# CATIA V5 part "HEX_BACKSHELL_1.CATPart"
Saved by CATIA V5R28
Part number: HEX_BACKSHELL_1
Revision: ---
Publications: "Logical Termination.1", "BaCP", "Face_generated(BaCP)", "Axis_generated(BaCP)", "Face_generated(BaCP).1", "BCP", "BCPRPoint_generated(BCP)", "BCPPlane_generated(BCP)", "SOCK", "SOCKRPoint_generated(SOCK)", "SOCKRLine_generated(SOCK)"
Bounding box of the stored display mesh (mm): x 0 to 28.448, y -13.335 to 13.335, z -24.638 to 12.832
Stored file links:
  C:\Users\ajc8720\Documents\BOEING_WORK\0001-2CES\004-AP242\Boeing-Generic_Harness_R3\HEX_BACKSHELL_1.CATPart
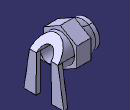
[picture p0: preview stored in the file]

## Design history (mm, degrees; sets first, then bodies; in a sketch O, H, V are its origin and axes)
Parameters
  PartNumber = "HEX_BACKSHELL_1"
Set1 "EGF"
  Set2 "BaCP"
    Point1 "BaCPRPoint": (6.604, 0, 0)
    Plane1 "BaCPCPlane": type OffsetPt, RefPlane yz-plane, RefPoint Point1
    Line1 "BaCPOLine": type PtDir, RefPoint Point1, Direction zx-plane, Start 0, End 12.7
  Set3 "BCP"
    Point2 "BCPRPoint": (27.051, 0, -24.638)
    Plane2 "BCPPlane": type OffsetPt, RefPlane xy-plane, RefPoint Point2
  Set4 "SOCK"
    Point3 "SOCKRPoint": (27.051, 0, -24.638)
    Line2 "SOCKRLine": type PtDir, RefPoint Point3, Direction xy-plane, Start 0, End 6.35
Body1 (main body)
  Sketch1 on zx-plane, origin (0, 0, 0), H (-1, 0, 0), V (0, 0, 1)
    point P1 (-8.001, 11.1125)
    line L1 (-8.001, 11.1125) -> (-2.54, 9.017)
    point P2 (-2.54, 9.017)
    line L2 (-2.54, 9.017) -> (0, 9.017)
    line L3 (0, 9.017) -> (0, 0)
    line L4 (0, 0) -> (-8.001, 0)
    line L5 (-8.001, 0) -> (-8.001, 11.1125)
    reference intersected line E1 through (0, 0) direction (-1, 0) from xy-plane
    reference intersected line E2 through (0, 0) direction (0, -1) from yz-plane
    reference intersected line E3 through (0, 0) direction (-1, 0) from xy-plane
    reference intersected line E4 through (0, 0) direction (0, -1) from yz-plane
    reference intersected line E5 through (0, 0) direction (-1, 0) from xy-plane
    reference intersected line E6 through (0, 0) direction (0, -1) from yz-plane
    distance L2 E3 = 9.017
    distance L5 E4 = 8.001
    distance P1 E5 = 11.1125
    distance P2 E6 = 2.54
    horizontal: L2 H, L4 H
    vertical: L3 V, L5 V
    coincidence: L4 E1, L3 E2
  Shaft1 "ShaftCoupling": profile Sketch1, axis Sketch1.H, angle 360
  Sketch2 on yz-plane, origin (0, 0, 0), H (0, 1, 0), V (0, 0, 1)
    point P1 (11.1125, 6.4158)
    point P2 (0, 12.8316)
    point P3 (-11.1125, 6.4158)
    point P4 (-11.1125, -6.4158)
    point P5 (0, -12.8316)
    point P6 (11.1125, -6.4158)
    point P7 (5.5563, 9.6237)
    line L1 (11.1125, 6.4158) -> (0, 12.8316)
    line L2 (0, 12.8316) -> (-11.1125, 6.4158)
    line L3 (-11.1125, 6.4158) -> (-11.1125, -6.4158)
    line L4 (-11.1125, -6.4158) -> (0, -12.8316)
    line L5 (0, -12.8316) -> (11.1125, -6.4158)
    line L6 (11.1125, -6.4158) -> (11.1125, 6.4158)
    construction line L7 (0, 0) -> (5.5563, 9.6237)
    construction circle A1 centre (0, 0) radius 12.8316
    construction arc A2 centre (0, -12.8316) radius 12.8316 from (-11.1125, -6.4158) to (11.1125, -6.4158) cw
    construction arc A3 centre (0, 12.8316) radius 12.8316 from (-11.1125, 6.4158) to (11.1125, 6.4158) ccw
    reference intersected line E1 through (0, 0) direction (0, 1) from zx-plane
    distance L1 L4 = 22.225
    coincidence: A1 P1, A1 P2, A1 P3, A1 P4, A1 P5, A1 P6, A2 O, A3 O, P2 E1
    midpoint: P7 L1
  Pad1 "PadHex": profile Sketch2, direction (1, 0, 0), length 17.399, opposite side length -8.001
  Sketch3 on yz-plane, origin (0, 0, 0), H (0, 1, 0), V (0, 0, 1)
    circle A1 centre (0, 0) radius 7.493
    radius A1 = 7.493
  Pocket1 "PocketCoupling": profile Sketch3, direction (1, 0, 0), length 6.604
  Sketch4 on yz-plane, origin (0, 0, 0), H (0, 1, 0), V (0, 0, 1)
    circle A1 centre (0, 0) radius 9.5631
    radius A1 = 9.5631
  Pad2 "PadRearDiameter": profile Sketch4, direction (1, 0, 0), length 28.448, opposite side length -9.144
  Sketch5 on zx-plane, origin (0, 0, 0), H (-1, 0, 0), V (0, 0, 1)
    point P1 (-19.685, 9.5631)
    line L1 (-19.685, 9.5631) -> (-28.448, 0)
    point P2 (-28.448, 0)
    line L2 (-28.448, 0) -> (-28.448, 9.5631)
    line L3 (-28.448, 9.5631) -> (-19.685, 9.5631)
    reference intersected line E1 through (0, 0) direction (-1, 0) from xy-plane
    reference intersected line E2 through (0, 0) direction (0, -1) from yz-plane
    reference intersected line E3 through (0, 0) direction (0, -1) from yz-plane
    distance L3 E1 = 9.5631
    distance L2 E2 = 28.448
    distance P1 E3 = 19.685
    coincidence: P2 H
    vertical: L2 V
    horizontal: L3 H
  Pocket2 "PocketTopAngle": profile Sketch5, direction (0, -1, 0), length 9.5631, opposite side length 9.5631
  Sketch6 on yz-plane, origin (0, 0, 0), H (0, 1, 0), V (0, 0, 1)
    point P1 (9.5631, 0)
    line L1 (9.5631, 0) -> (13.335, -24.638)
    point P2 (13.335, -24.638)
    line L2 (13.335, -24.638) -> (5.207, -24.638)
    point P3 (5.207, -24.638)
    line L3 (5.207, -24.638) -> (4.953, 0)
    point P4 (4.953, 0)
    line L4 (4.953, 0) -> (9.5631, 0)
    point P5 (-4.953, 0)
    line L5 (-4.953, 0) -> (-5.207, -24.638)
    point P6 (-5.207, -24.638)
    line L6 (-5.207, -24.638) -> (-13.335, -24.638)
    point P7 (-13.335, -24.638)
    line L7 (-13.335, -24.638) -> (-9.5631, 0)
    point P8 (-9.5631, 0)
    line L8 (-9.5631, 0) -> (-4.953, 0)
    reference intersected line E1 through (0, 0) direction (-1, 0) from xy-plane
    reference intersected line E2 through (0, 0) direction (-1, 0) from xy-plane
    reference intersected line E3 through (0, 0) direction (0, 1) from zx-plane
    reference intersected line E4 through (0, 0) direction (0, 1) from zx-plane
    reference intersected line E5 through (0, 0) direction (-1, 0) from xy-plane
    reference intersected line E6 through (0, 0) direction (0, 1) from zx-plane
    length L6 = 8.128
    length L2 = 8.128
    distance P2 P7 = 26.67
    distance P1 P8 = 19.1262
    distance P4 P5 = 9.906
    distance L6 E5 = 24.638
    horizontal: L2 H, L4 H, L6 H, L8 H
    coincidence: P6 L2, L8 E1, L4 E2
    symmetry: P5 P4 E3, P8 P1 E4, P6 P3 E6
  Pad3 "PadSupports": profile Sketch6, direction (1, 0, 0), length 28.448, opposite side length -25.654
  Sketch7 on yz-plane, origin (0, 0, 0), H (0, 1, 0), V (0, 0, 1)
    point P1 (-4.953, 0)
    line L1 (-4.953, 0) -> (-5.207, -24.638)
    point P2 (-5.207, -24.638)
    line L2 (-5.207, -24.638) -> (5.207, -24.638)
    point P3 (5.207, -24.638)
    line L3 (5.207, -24.638) -> (4.953, 0)
    point P4 (4.953, 0)
    line L4 (4.953, 0) -> (-4.953, 0)
    reference intersected line E1 through (0, 0) direction (0, 1) from zx-plane
    reference intersected line E2 through (0, 0) direction (-1, 0) from xy-plane
    reference intersected line E3 through (0, 0) direction (0, 1) from zx-plane
    length L4 = 9.906
    length L2 = 10.414
    distance L2 E2 = 24.638
    coincidence: P1 H, P4 H
    horizontal: L2 H, L4 H
    symmetry: P3 P2 E1, P1 P4 E3
  Pocket3 "PocketForWires": profile Sketch7, direction (1, 0, 0), length 28.448, opposite side length -25.654
  Sketch8 on yz-plane, origin (0, 0, 0), H (0, 1, 0), V (0, 0, 1)
    circle A1 centre (0, 0) radius 4.953
    radius A1 = 4.953
  Pocket4 "PocketThruHole": profile Sketch8, direction (1, 0, 0), length 28.448
  Sketch9 on zx-plane, origin (0, 0, 0), H (-1, 0, 0), V (0, 0, 1)
    point P1 (-19.685, -9.5631)
    line L1 (-19.685, -9.5631) -> (-25.654, -5.08)
    point P2 (-25.654, -5.08)
    line L2 (-25.654, -5.08) -> (-25.654, -9.5631)
    line L3 (-25.654, -9.5631) -> (-19.685, -9.5631)
    reference intersected line E1 through (0, 0) direction (0, -1) from yz-plane
    reference intersected line E2 through (0, 0) direction (-1, 0) from xy-plane
    reference intersected line E3 through (0, 0) direction (0, -1) from yz-plane
    reference intersected line E4 through (0, 0) direction (-1, 0) from xy-plane
    distance L2 E1 = 25.654
    distance L3 E2 = 9.5631
    distance P1 E3 = 19.685
    distance P2 E4 = 5.08
    vertical: L2 V
    horizontal: L3 H
  Pocket5: profile Sketch9, direction (0, -1, 0), length 9.5631, opposite side length 9.5631
Body2 "BaCP"
  Sketch10 "Sketch" on Plane1, origin (6.604, 0, 0), H (0, 1, 0), V (0, 0, 1)
    line L1 (-0.672, 0.762) -> (0.672, 0.762)
    point P1 (-0.672, 0.762)
    point P2 (0.672, 0.762)
    arc A1 centre (0, 0) radius 1.016 from (-1.016, 0) to (1.016, 0) ccw
    point P3 (0, 0)
    point P4 (-1.016, 0)
    point P5 (1.016, 0)
    reference projected point E1 (0, 0) from Point1
    arc A2 centre (0, 0) radius 1.016 from (1.016, 0) to (0.672, 0.762) ccw
    point P6 (0, 0)
    point P7 (1.016, 0)
    point P8 (0.672, 0.762)
    arc A3 centre (0, 0) radius 1.016 from (-0.672, 0.762) to (-1.016, 0) ccw
    point P9 (0, 0)
    point P10 (-0.672, 0.762)
    point P11 (-1.016, 0)
    reference projected point E2 (0, 0) from Point1
    reference projected point E3 (0, 0) from Point1
    length L1 = 1.344
    radius A1 = 1.016
    radius A3 = 1.016
    radius A2 = 1.016
    distance L1 P5 = 0.762
    distance P4 L1 = 0.762
    distance P7 L1 = 0.762
    distance P11 L1 = 0.762
    coincidence: P3 E1, P6 E2, P9 E3, P8 P2, P10 P1
    horizontal: L1 H
  Pad4: profile Sketch10, direction (1, 0, 0), length 0.508, opposite side up to Plane1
